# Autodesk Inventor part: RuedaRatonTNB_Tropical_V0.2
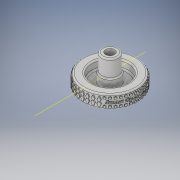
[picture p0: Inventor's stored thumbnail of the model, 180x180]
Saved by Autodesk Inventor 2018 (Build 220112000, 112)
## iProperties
Created: 2020-11
Part Number: RuedaRatonTNB_Tropical_V0.2
Material: Generic
Document SubType Name: Modeling
Designer: antonio
Density: 1 g/cm^3
Appearance: Default
Author: antonio
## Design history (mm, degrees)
sketch "Sketch1"
  geometry: C1 r 3.5 at (0, 0); 1 further point
  constraints: 1 centre point, 1 coincident
  dimensions: "d0" = 7 diameter of C1
extrude "Extrusion1" new body sketch "Sketch1" distance "d1" = 7.5; taper "d2" = 0 deg
sketch "Sketch2"
  geometry: C1 r 1.9 at (0, 0); 1 further point
  constraints: 1 centre point, 1 coincident
  dimensions: "d3" = 3.8 diameter of C1
sketch "Sketch3"
  geometry: C1 r 11.4 at (0, 0); 1 further point
  constraints: 1 centre point, 1 coincident
  dimensions: "d4" = 22.8 diameter of C1
extrude "Extrusion2" join sketch "Sketch3" distance "d5" = 5.7; taper "d6" = 0 deg
extrude "Extrusion3" cut sketch "Sketch2" distance "d7" = 10; taper "d8" = 0 deg
sketch "Sketch4"
  geometry: C1 r 11.4 at (0, 0) reference; C2 r 3.5 at (0, 0) reference; C3 r 4 at (0, 0); C4 r 3.5 at (0, 0) reference; C5 r 7.65 at (0, 0); 1 further point
  constraints: 2 centre point, 1 coincident
  dimensions: "d9" = 0.5 radial gap between concentric circles of C2 C3; "d10" = 15.3 diameter of C5
extrude "Extrusion4" cut sketch "Sketch4" distance "d11" = 3.5; taper "d12" = 0 deg
sketch "Sketch5"
  geometry: C1 r 1.4 at (0, 0); 1 further point
  constraints: 1 centre point, 1 coincident
  dimensions: "d13" = 2.8 diameter of C1
extrude "Extrusion5" join sketch "Sketch5" distance "d14" = 3; taper "d15" = 0 deg
sketch "Sketch6"
  geometry: L1 (-0.7, -0.404)-(-0.7, 0.404); L2 (-0.7, 0.404)-(0, 0.808); L3 (0, 0.808)-(0.7, 0.404); L4 (0.7, 0.404)-(0.7, -0.404); L5 (0.7, -0.404)-(0, -0.808); L6 (0, -0.808)-(-0.7, -0.404); 2 further points
  constraints: 12 end point, 1 coincident, 1 vertical, 13 other
  dimensions: "d16" = 1.4 distance between parallel lines of L4 L1
extrude "Extrusion6" join sketch "Sketch6" distance "d17" = 3.2; taper "d18" = 0 deg
fillet "Fillet1" dims "d19" = 0.6, "d20" = 0.4
workplane "Work Plane1"
sketch "Sketch7"
  geometry: L1 (-2.067, 10.387)-(-2.067, -9.613); L2 (-2.067, -9.613)-(-4.033, -9.613); L3 (-4.033, -9.613)-(-4.033, 10.387); L4 (-4.033, 10.387)-(-2.067, 10.387); L5 (-0.668, 10.565)-(-0.956, 10.065); L6 (-0.956, 10.065)-(-1.534, 10.065); L7 (-1.534, 10.065)-(-1.822, 10.565); L8 (-1.822, 10.565)-(-1.534, 11.065); L9 (-1.534, 11.065)-(-0.956, 11.065); L10 (-0.956, 11.065)-(-0.668, 10.565); L11 (-5.1, 11.4)-(-5.1, -11.4) reference; L12 (-0.6, -11.4)-(-0.6, 11.4) reference; L13 (-0.668, 8.945)-(-0.956, 8.445); L14 (-0.956, 8.445)-(-1.534, 8.445); L15 (-1.534, 8.445)-(-1.822, 8.945); L16 (-1.822, 8.945)-(-1.534, 9.445); L17 (-1.534, 9.445)-(-0.956, 9.445); L18 (-0.956, 9.445)-(-0.668, 8.945); L19 (-0.668, 7.325)-(-0.956, 6.825); L20 (-0.956, 6.825)-(-1.534, 6.825); L21 (-1.534, 6.825)-(-1.822, 7.325); L22 (-1.822, 7.325)-(-1.534, 7.825); L23 (-1.534, 7.825)-(-0.956, 7.825); L24 (-0.956, 7.825)-(-0.668, 7.325); L25 (-0.668, 5.705)-(-0.956, 5.205); L26 (-0.956, 5.205)-(-1.534, 5.205); L27 (-1.534, 5.205)-(-1.822, 5.705); L28 (-1.822, 5.705)-(-1.534, 6.205); L29 (-1.534, 6.205)-(-0.956, 6.205); L30 (-0.956, 6.205)-(-0.668, 5.705); L31 (-0.668, 4.085)-(-0.956, 3.585); L32 (-0.956, 3.585)-(-1.534, 3.585); L33 (-1.534, 3.585)-(-1.822, 4.085); L34 (-1.822, 4.085)-(-1.534, 4.585); L35 (-1.534, 4.585)-(-0.956, 4.585); L36 (-0.956, 4.585)-(-0.668, 4.085); L37 (-0.668, 2.465)-(-0.956, 1.965); L38 (-0.956, 1.965)-(-1.534, 1.965); L39 (-1.534, 1.965)-(-1.822, 2.465); L40 (-1.822, 2.465)-(-1.534, 2.965); L41 (-1.534, 2.965)-(-0.956, 2.965); L42 (-0.956, 2.965)-(-0.668, 2.465); L43 (-0.668, 0.845)-(-0.956, 0.345); L44 (-0.956, 0.345)-(-1.534, 0.345); L45 (-1.534, 0.345)-(-1.822, 0.845); L46 (-1.822, 0.845)-(-1.534, 1.345); L47 (-1.534, 1.345)-(-0.956, 1.345); L48 (-0.956, 1.345)-(-0.668, 0.845); L49 (-0.668, -0.775)-(-0.956, -1.275); L50 (-0.956, -1.275)-(-1.534, -1.275); L51 (-1.534, -1.275)-(-1.822, -0.775); L52 (-1.822, -0.775)-(-1.534, -0.275); L53 (-1.534, -0.275)-(-0.956, -0.275); L54 (-0.956, -0.275)-(-0.668, -0.775); L55 (-0.668, -2.395)-(-0.956, -2.895); L56 (-0.956, -2.895)-(-1.534, -2.895); L57 (-1.534, -2.895)-(-1.822, -2.395); L58 (-1.822, -2.395)-(-1.534, -1.895); L59 (-1.534, -1.895)-(-0.956, -1.895); L60 (-0.956, -1.895)-(-0.668, -2.395); L61 (-0.668, -4.015)-(-0.956, -4.515); L62 (-0.956, -4.515)-(-1.534, -4.515); L63 (-1.534, -4.515)-(-1.822, -4.015); L64 (-1.822, -4.015)-(-1.534, -3.515)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; 29 further points
  constraints: 336 end point, 2 horizontal, 1 collinear, 1 vertical, 365 other
  dimensions: "d22" = 20 distance of L1.start L1.end; "d28" = 1 distance between parallel lines of L9 L6; "d31" = 1.62 distance of point (-1.245, 10.565) point (-1.245, 8.945); "d34" = 3.2 distance of point (-1.245, 10.565) point (-4.445, 10.565)
emboss "Emboss1" sketch "Sketch7" dims "d23" = 0.4, "d24" = 0
pattern_circular "Circular Pattern1" dims angle "d26" = 360 deg
workplane "Work Plane2"
sketch "Sketch8"
  geometry: L1 (0, -0.891)-(0, -4.891); L2 (0, -0.891)-(4, -0.891); L3 (10.8, -5.7)-(-10.8, -5.7) reference; L4 (-1.4, -6.3)-(-1.4, -8.7) reference; L5 (-1.9, -0.891)-(-1.9, -4.891); L6 (-3.8, -0.891)-(-3.8, -4.891); L7 (-5.7, -0.891)-(-5.7, -4.891); L8 (1.9, -0.891)-(1.9, -4.891); L9 (0, -0.891)-(0, -4.891); L10 (-1.9, -0.891)-(-1.9, -4.891); L11 (-3.8, -0.891)-(-3.8, -4.891); L12 (3.8, -0.891)-(3.8, -4.891); L13 (1.9, -0.891)-(1.9, -4.891); L14 (0, -0.891)-(0, -4.891); L15 (-1.9, -0.891)-(-1.9, -4.891); L16 (5.7, -0.891)-(5.7, -4.891); L17 (3.8, -0.891)-(3.8, -4.891); L18 (1.9, -0.891)-(1.9, -4.891); L19 (0, -0.891)-(0, -4.891); 193 further points
  constraints: 34 end point, 33 horizontal, 6 symmetric about line, 3 vertical, 1 perpendicular, 481 other
  dimensions: "d38" = 4 distance of L1.start L1.end; "d39" = 90 deg angle of L1 L2 (derived); "d44" = 1.9 distance of L1.start L5.start; "d47" = 1.9 distance of L1.start L8.start
emboss "Emboss2" sketch "Sketch8" dims "d40" = 0.4, "d41" = 0
pattern_circular "Circular Pattern2" dims angle "d51" = 360 deg
fillet "Fillet2" dims "d53" = 0.1
body "Solid1"
node "Projected Loop1"
node "Projected Loop2"
